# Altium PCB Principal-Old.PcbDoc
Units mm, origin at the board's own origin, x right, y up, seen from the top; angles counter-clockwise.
Board outline 152.4 x 101.6 mm, 2 copper layers (Top Layer, Bottom Layer); 39 components, 56 nets, 199 pads, 48 vias.
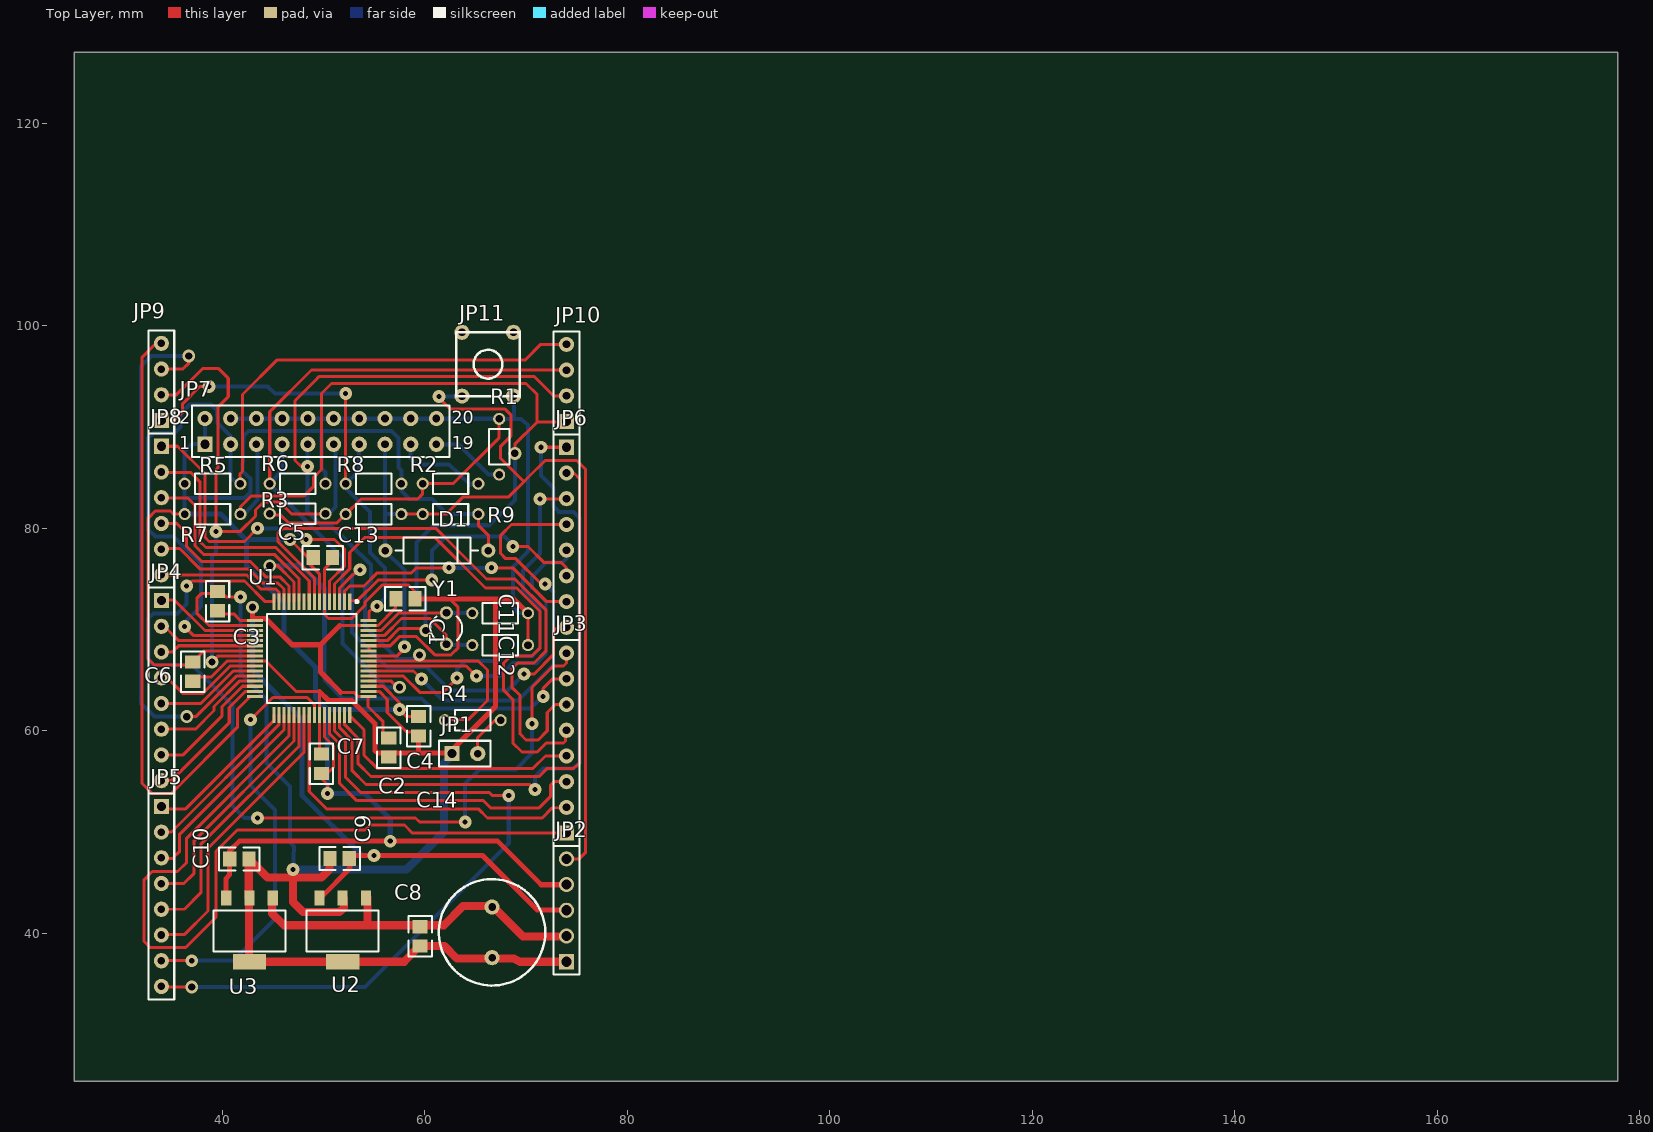
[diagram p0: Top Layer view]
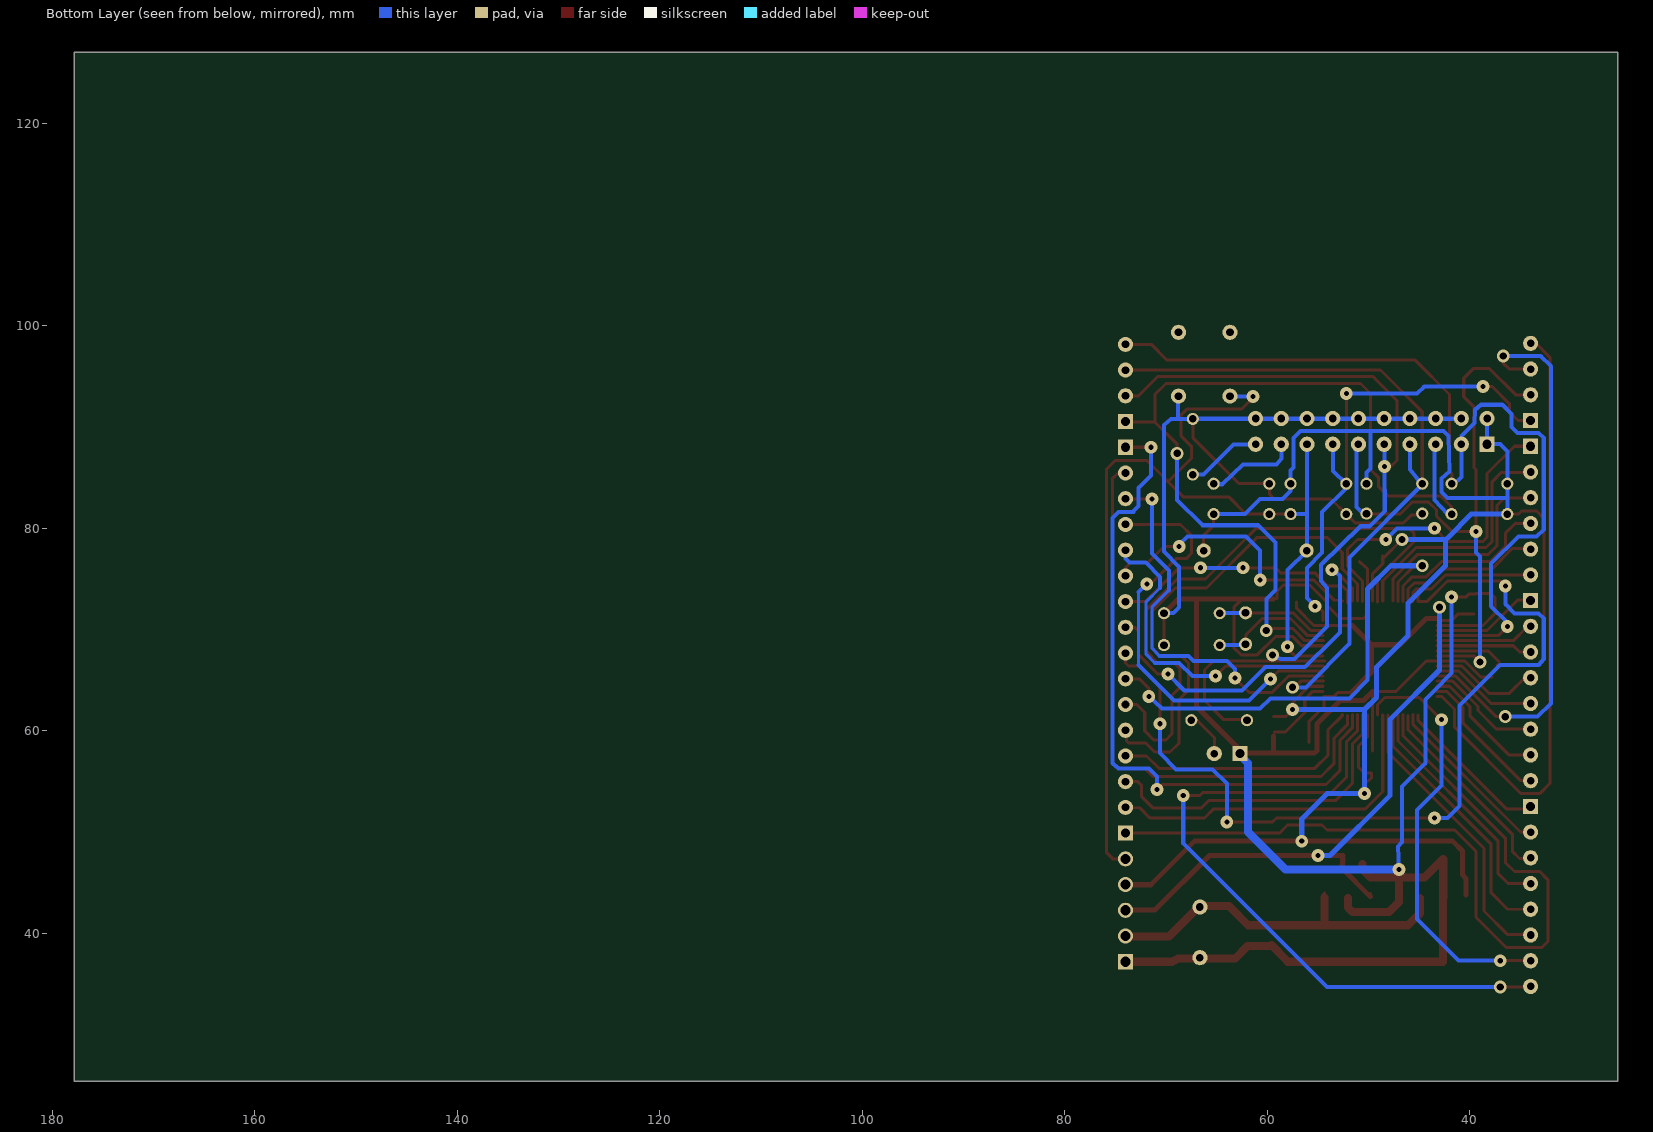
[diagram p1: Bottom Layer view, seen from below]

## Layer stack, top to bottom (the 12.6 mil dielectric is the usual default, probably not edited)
Top Layer: signal copper 0.0356
Dielectric: dielectric 0.32, FR-4, Dk 4.8
Bottom Layer: signal copper 0.0356

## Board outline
25.4,25.4 177.8,25.4 177.8,127 25.4,127

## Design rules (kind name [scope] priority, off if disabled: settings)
Clearance [All] p1: gap=0.2
ComponentClearance [All] p1: gap=0.254 collisioncheckmode=0
PolygonConnect [All] p1: connectstyle=Relief reliefconductorwidth=0.254 reliefentries=4 polygonreliefangle="90 Angle"
RoomDefinition Principal1 [InComponentClass('Principal1')] p1: confinementstyle=ConfineIn formatcopy=TRUE outline 0,0 50.8,0 50.8,25.4 0,25.4
RoutingLayers [All] p1: top layer=Horizontal bottom layer=Vertical
RoutingVias [All] p1: holewidth=0.711 width=1.27 viastyle="Through Hole" minholewidth=0.711 minwidth=1.27 maxholewidth=0.711 maxwidth=1.27
SolderMaskExpansion [All] p1: expansion=0.102
TestPointUsage [All] p1: valid=0 allowmultiple=FALSE
Testpoint [All] p1: side=15 testpointundercomponent=TRUE minsize=1.016 maxsize=2.54 preferedsize=1.524 minholesize=0 maxholesize=1.016 preferedholesize=0.813 testpointgrid=0.025 style=1023 order=1234567890
Width [All] p1: maxlimit=0.8 minlimit=0.2 preferedwidth=0.2 toplayer_prefwidth=0.3 bottomlayer_prefwidth=0.4 minimp=50.000000 maximp=50.000000 favimp=50.000000
16 further rules are at their usual default settings.

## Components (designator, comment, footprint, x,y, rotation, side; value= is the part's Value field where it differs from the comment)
C1 "Cap" R2012-0805 58.1,73.05 r180 top
C2 "Cap" R2012-0805 56.45,58.35 r90 top
C3 "Cap" R2012-0805 39.55,72.8 r270 top
C4 "Cap" R2012-0805 59.4,60.45 r90 top
C5 "Cap" R2012-0805 49.95,77.1 r180 top
C6 "Cap" R2012-0805 37.1,65.85 r90 top
C7 "Cap" R2012-0805 49.8,56.75 r270 top
C8 "Cap" R2012-0805 59.55,39.7 r90 top
C9 "Cap" R2012-0805 51.6,47.4 r0 top
C10 "Cap" R2012-0805 41.7,47.35 r180 top
C11 "Cap" "Res 5mm" 64.7,71.614 r0 top
C12 "Cap" "Res 5mm" 64.7,68.464 r0 top
C13 "Cap" "Res 5mm" 57.7,81.4 r180 top
C14 "Cap Pol1" RB5-10.5 66.65,40.1 r270 top
D1 "Diode" DIODE-0.4 61.2,77.8 r0 top
JP1 "JTAG" HDR1X2 62.7,57.75 r0 top
JP2 "Header 5" HDR1X5 74,37.2 r90 top
JP3 "Header 8" HDR1X8 74,49.9 r90 top
JP4 "Header 8" HDR1X8 34,72.86 r270 top
JP5 "Header 8" HDR1X8 34,52.54 r270 top
JP6 "Header 8" HDR1X8 74,88 r270 top
JP7 "JTAG P5" HDR2X10 38.3,88.3 r0 top
JP8 "Header 6" HDR1X6 34,88.1 r270 top
JP9 "Header 4" HDR1X4 34,90.64 r90 top
JP10 "Header 4" HDR1X4 74,90.54 r90 top
JP11 "Header 2" SW1 69.4,99.35 r180 top
R1 "Res1" "Res 5mm" 67.35,85.3 r90 top
R2 "Res1" "Res 5mm" 65.3,84.4 r180 top
R3 "Res1" "Res 5mm" 50.2,81.45 r180 top
R4 "Res1" "Res 5mm" 62,61.05 r0 top
R5 "Res1" "Res 5mm" 36.3,84.4 r0 top
R6 "Res1" "Res 5mm" 50.2,84.4 r180 top
R7 "Res1" "Res 5mm" 36.3,81.4 r0 top
R8 "Res1" "Res 5mm" 57.7,84.4 r180 top
R9 "Res1" "Res 5mm" 59.8,81.4 r0 top
U1 "LPC2114/LPC2124" F-QFP10X10-G64/P.5N 48.85,67.15 r270 top
U2 "LD1117S18" SOT223 58,37.2 r180 top
U3 "LD1117S33" SOT223 48.8,37.2 r180 top
Y1 "XTAL 16Mhz" BCY-W2/D3.1 62.15,70.1 r180 top

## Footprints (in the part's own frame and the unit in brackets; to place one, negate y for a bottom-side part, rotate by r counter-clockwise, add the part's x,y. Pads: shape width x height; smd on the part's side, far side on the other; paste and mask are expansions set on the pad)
BCY-W2/D3.1 [mm]
  round 1.3 hole 0.75: 1(0,1.55) 2(0,-1.55)
  silkscreen extent -1.55,-1.19 1.55,1.17
DIODE-0.4 [mm]
  round 1.4 hole 0.75: 1(-5.08,0) 2(5.08,0)
  silkscreen extent -4.06,-1.27 4.06,1.27
F-QFP10X10-G64/P.5N [mm]
  rect 1.6x0.3 smd: 1(-5.6,3.75) 2(-5.6,3.25) 3(-5.6,2.75) 4(-5.6,2.25) 5(-5.6,1.75) 6(-5.6,1.25) 7(-5.6,0.75) 8(-5.6,0.25) 9(-5.6,-0.25) 10(-5.6,-0.75) 11(-5.6,-1.25) 12(-5.6,-1.75) 13(-5.6,-2.25) 14(-5.6,-2.75) 15(-5.6,-3.25) 16(-5.6,-3.75) 33(5.6,-3.75) 34(5.6,-3.25) 35(5.6,-2.75) 36(5.6,-2.25) 37(5.6,-1.75) 38(5.6,-1.25) 39(5.6,-0.75) 40(5.6,-0.25) 41(5.6,0.25) 42(5.6,0.75) 43(5.6,1.25) 44(5.6,1.75) 45(5.6,2.25) 46(5.6,2.75) 47(5.6,3.25) 48(5.6,3.75)
  rect 0.3x1.6 smd: 17(-3.75,-5.6) 18(-3.25,-5.6) 19(-2.75,-5.6) 20(-2.25,-5.6) 21(-1.75,-5.6) 22(-1.25,-5.6) 23(-0.75,-5.6) 24(-0.25,-5.6) 25(0.25,-5.6) 26(0.75,-5.6) 27(1.25,-5.6) 28(1.75,-5.6) 29(2.25,-5.6) 30(2.75,-5.6) 31(3.25,-5.6) 32(3.75,-5.6) 49(3.75,5.6) 50(3.25,5.6) 51(2.75,5.6) 52(2.25,5.6) 53(1.75,5.6) 54(1.25,5.6) 55(0.75,5.6) 56(0.25,5.6) 57(-0.25,5.6) 58(-0.75,5.6) 59(-1.25,5.6) 60(-1.75,5.6) 61(-2.25,5.6) 62(-2.75,5.6) 63(-3.25,5.6) 64(-3.75,5.6)
  silkscreen extent -5.72,-4.4 4.4,4.58
HDR1X2 [mm]
  rect 1.5x1.5 hole 0.9: 1(0,0)
  round 1.5 hole 0.75: 2(2.54,0)
  silkscreen extent -1.27,-1.27 3.81,1.27
HDR1X4 [mm]
  rect 1.5x1.5 hole 0.9: 1(0,0)
  round 1.5 hole 0.75: 2(2.54,0) 3(5.08,0) 4(7.62,0)
  silkscreen extent -1.27,-1.27 8.89,1.27
HDR1X5 [mm]
  rect 1.5x1.5 hole 1: 1(0,0)
  round 1.5 hole 1: 2(2.54,0) 3(5.08,0) 4(7.62,0) 5(10.16,0)
  silkscreen extent -1.27,-1.27 11.43,1.27
HDR1X6 [mm]
  rect 1.5x1.5 hole 0.9: 1(0,0)
  round 1.5 hole 0.75: 2(2.54,0) 3(5.08,0) 4(7.62,0) 5(10.16,0) 6(12.7,0)
  silkscreen extent -1.27,-1.27 13.97,1.27
HDR1X8 [mm]
  rect 1.5x1.5 hole 0.9: 1(0,0)
  round 1.5 hole 0.75: 2(2.54,0) 3(5.08,0) 4(7.62,0) 5(10.16,0) 6(12.7,0) 7(15.24,0) 8(17.78,0)
  silkscreen extent -1.27,-1.27 19.05,1.27
HDR2X10 [mm]
  rect 1.5x1.5 hole 0.9: 1(0,0)
  round 1.5 hole 0.75: 2(0,2.54) 3(2.54,0) 4(2.54,2.54) 5(5.08,0) 6(5.08,2.54) 7(7.62,0) 8(7.62,2.54) 9(10.16,0) 10(10.16,2.54) 11(12.7,0) 12(12.7,2.54) 13(15.24,0) 14(15.24,2.54) 15(17.78,0) 16(17.78,2.54) 17(20.32,0) 18(20.32,2.54) 19(22.86,0) 20(22.86,2.54)
  silkscreen extent -1.27,-1.27 24.13,3.81
R2012-0805 [mm]
  rect 1.3x1.5 smd: 1(-0.95,0) 2(0.95,0)
  silkscreen extent -2,-1.15 2,1.15
RB5-10.5 [mm]
  round 1.5 hole 0.75: 1(-2.5,0) 2(2.5,0)
  silkscreen extent -5.25,-5.25 5.25,5.25
"Res 5mm" [mm]
  round 1.2 hole 0.75: 1(0,0) 2(5.5,0)
  silkscreen extent 1,-1.02 4.5,1.02
SOT223 [mm]
  rect 1x1.5 smd: 1(3.8,-6.3) 3(8.4,-6.3) 4(6.1,-6.3)
  rect 3.3x1.5 smd: 4(6.096,0)
  silkscreen extent 2.54,-5.08 9.65,-1.02
SW1 [mm]
  round 1.5 hole 0.75: 1(0.635,6.3) 1(0.635,0) 2(5.715,6.3) 2(5.715,0)
  silkscreen extent 0,0 6.3,6.3

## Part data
C1 C2 C3 C4 C5 C6 C7 C8 C9 C10 C11 C12 C13: "Capacitor"
C14: "Polarized Capacitor (Radial)"
D1: "Default Diode"
JP1 JP2: library part "Header 2", "Header, 2-Pin"
JP3 JP4 JP5 JP6: "Header, 8-Pin"
JP7: library part "Header 10X2", "Header, 10-Pin, Dual row"
JP8: "Header, 6-Pin"
JP9: library part "Header 8", "Header, 8-Pin"
JP10: "Header, 4-Pin"
JP11: "Header, 2-Pin"
R1 R2 R3 R4 R5 R6 R7 R8 R9: "Resistor"
U2 U3: library part LF27ACDT, "Very Low Drop Voltage Regulator with Inhibit"
Y1: library part XTAL, "Crystal Oscillator"

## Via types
v1: diameter 1.27, hole 0.5, Top Layer to Bottom Layer, 37 vias
v2: diameter 1.27, hole 0.711, Top Layer to Bottom Layer, 11 vias

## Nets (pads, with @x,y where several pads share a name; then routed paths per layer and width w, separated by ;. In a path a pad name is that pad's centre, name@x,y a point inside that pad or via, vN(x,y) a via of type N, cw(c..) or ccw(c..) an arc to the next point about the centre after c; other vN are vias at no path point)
GND: C1.1 C2.1 C3.1 C4.1 C5.1 C6.1 C7.1 C8.1 C9.1 C10.1 C11.2 C12.2 C13.2 C14.2 JP1.1 JP2.1 JP7.4 JP7.6 JP7.8 JP7.10 JP7.12 JP7.14 JP7.16 JP7.18 JP7.20 JP11.1@68.765,93.05 R1.2 R2.2 R3.2 U1.6 U1.18 U1.25 U1.42 U1.50 U1.58 U1.59 U2.4 U3.4 | length 319.4
  Top Layer w0.3: C6.1@37.8,65.3 38.9,65.3 40.5,66.9 U1.25 44.3,66.9 47.3,63.9 49.6,63.9 C7.1@49.6,58 ; v1@42.1,73.2 40.4,73.2 40.1,73.5 39.45,73.5 39.4,73.55 37.95,73.55 37.5,73.1 37.5,71.6 38.7,70.4 41.5,70.4 U1.18 ; R3.2@44.85,81.3 45.8,81.3 46.6,80.5 51.3,80.5 C13.2 53.7,82.9 59.3,82.9 59.8,83.4 R2.2 62.8,84.4 67.35,88.95 R1.2@67.35,90.3 ; C5.1@50.9,76.7 50.826,76.635 50.1,76 50.1,71.5 50.5,71.1 52.8,71.1 54.1,72.4 54.1,72.7 55.8,74.4 58.4,74.4 59.05,73.75 C1.1 ; U1.50@54.5,63.9 55.5,63.9 56.3,63.1 56.3,61.8 58.2,59.9 C4.1@59.3,59.9 ; U1.58@54.5,67.9 54.5,68.4 56.6,68.4 57.5,69.3 59.2,69.3 61,67.5 62.6,67.5 63.3,68.2 63.3,72.2 62.5,73 ; JP7.20@61.144,90.816 JP7.20@61.144,90.83 ; C12.2 C11.2
  Top Layer w0.5: 49.6,63.9 50.5,63 52.8,63 55.1,60.7 55.1,58 55.4,57.8 JP1.1@62.3,57.8 ; 59.4,57.8 C4.1 ; C1.1@59.4,73 67,73 ; JP1.1 JP1.1@62.3,57.8 ; C11.2 68.814,73 67,73 ; JP1.1@62.3,57.8 62.7,58.1 67,62.4 67,73
  Top Layer w0.8: C10.1@42.626,47.348 42.626,43.524 42.654,43.496 42.654,37.2 52.054,37.2 58,37.2 58,37.25 C8.1@59.6,38.85 ; C10.1@42.637,47.337 44.474,45.5 49.8,45.5 50.6,46.3 C9.1@50.6,46.847 ; 47,45.5 47,43.1 48,42.1 51.6,42.1 52.05,42.55 U2.4@52.05,43.5 ; v1(47,46.3) 47.1,45.5 ; C8.1 61.95,38.75 63.2,37.5 68.8,37.5 69.4,37.2 JP2.1
  Bottom Layer w0.4: JP7.4@40.824,90.816 67.834,90.816 67.85,90.8 69.5,90.8 70.2,90.2 70.2,83.3 70.2,77.7 68.7,76.2 68.7,72.2 69.286,71.614 C11.2 ; v1(41.8,73.2) 41.8,65.7 43.6,63.9 44.4,63.1 44.4,56.8 46.7,54.5 46.7,49 47.1,48.6 v1(47,46.3) ; JP11.1@68.765,93.05 68.8,93.015 68.8,90.8
  Bottom Layer w0.8: v1(47,46.3) 58.2,46.3 61.9,50 61.9,56.8 JP1.1@62.7,57.6
NetC1_2: C1.2 C2.2 C3.2 C9.2 JP2.3 U1.17 U1.49 U1.63 U2.3 | length 95.1
  Top Layer w0.3: C3.2@39.6,71.55 41.15,71.55 41.8,70.9 U1.17@43,70.9 ; 46.4,69 46.9,68.5 ; U2.3@49.834,43.628 U2.3@49.834,43.917 ; 51.6,70.4 55.4,70.4 57.1,72.1 C1.2@57.1,72.7 ; 51.7,63.8 53,63.8 53.4,63.4 U1.49 ; U1.49@54.4,63.4 54.4,62.4 55.9,60.9 C2.2@55.9,58.85
  Top Layer w0.5: v2(43,72.2) 43,71.1 44.3,71.1 46.9,68.5 49.7,68.5 ; U2.3@49.834,43.628 52.6,46.4 C9.2 ; 51.6,70.4 49.7,68.5 ; 51.7,63.8 49.7,65.8 49.7,68.5 ; C9.2@52.55,47.7 v1(55,47.7) 65.7,47.7 71.1,42.3 JP2.3@73.7,42.3
  Bottom Layer w0.5: v2(43,72.2) 43,66 47.9,61.1 47.9,53.6 53.8,47.7 v1(55,47.7)
NetC4_2: C4.2 C5.2 C6.2 C7.2 C10.2 D1.2 JP2.4 JP7.1 JP7.2 R5.1 R6.1 R7.1 R8.1 R9.2 U1.7 U1.23 U1.43 U1.51 U3.3 | length 211.6
  Top Layer w0.3: R7.1 35.2,81.4 34.9,81.7 33.4,81.7 32.7,81 32.7,67.1 33.3,66.5 35.4,66.5 36,66.5 C6.2@37.3,66.5 ; C6.2 38.2,67.9 U1.23 ; v2(46.7,78.9) 48.6,77 C5.2@48.65,76.95 ; C5.2@48.6,77.25 48.6,76.5 49.6,75.5 U1.7@49.6,72.8 ; U1.43 50.1,59.4 51,58.5 51,56.4 50.45,55.85 49.7,55.85 49.7,55.4 50.4,54.7 v1(50.4,53.8) ; U1.51@54.5,64.4 55.9,64.4 57.5,62.8 v1(57.5,62.1) 58.2,61.4 C4.2 ; R9.2 65.3,80.3 66.28,79.32 D1.2
  Top Layer w0.5: U3.3@40.4,43.8 40.4,45.4 40.726,45.775 40.726,48.126 41.7,49.1 67.2,49.1 71.5,44.8 JP2.4@73.7,44.8
  Bottom Layer w0.4: R7.1 36.3,84.2 36.3,87.6 37,88.3 JP7.1 ; 36.3,83 42.2,83 42.8,83.6 42.8,84.9 42,85.6 42.1,89.1 42.6,89.6 56.7,89.6 56.8,89.5 57.4,88.9 57.4,86 57.7,85.7 57.7,83.7 58.5,82.9 60.7,82.9 62.2,81.4 R9.2 ; JP7.1@38.284,88.276 JP7.2@38.284,90.816 ; 49.8,89.5 49.8,85.9 50.2,85.5 R6.1@50.2,84.35
  Bottom Layer w0.5: R7.1 39.9,81.4 42.1,79.1 42.4,78.9 ; v2(46.7,78.9) 42.4,78.9 ; v1(56.6,49.1) 56.6,51.3 54.1,53.8 v1(50.4,53.8) 50.4,62.1 ; v1(57.5,62.1) 56.059,62.104 53.9,62.1 50.4,62.1 ; 42.4,78.9 42.4,76.3 46.1,72.6 46.1,69.4 49.2,66.3 49.2,63.3 50.4,62.1
NetC8_2: C8.2 C14.1 JP2.2 U2.1 U3.1 | length 36.1
  Top Layer w0.3: U2.1@54.334,44.009 54.334,43.79 U2.1@54.553,43.79
  Top Layer w0.8: U3.1@44.95,43.5 44.934,41.966 46.1,40.8 61.9,40.8 63.8,42.7 66.7,42.7 69.7,39.7 JP2.2@73.8,39.7 ; 54.3,40.8 54.35,40.85 U2.1@54.35,43.55
NetC11_1: C11.1 U1.62 Y1.2 | length 11
  Top Layer w0.3: U1.62@54.5,69.9 55.7,69.9 57.414,71.614 Y1.2@62.114,71.614 ; C11.1 C11.1@64.75,71.664
  Bottom Layer w0.4: Y1.2@62.114,71.614 C11.1
NetC12_1: C12.1 U1.61 Y1.1 | length 12.5
  Top Layer w0.3: U1.61@54.5,69.4 56,69.4 57.7,71.1 60.5,71.1 62.1,69.5 62.184,68.55 Y1.1@62.184,68.514 ; C12.1@64.65,68.514 C12.1
  Bottom Layer w0.4: Y1.1@62.236,68.464 C12.1
NetC13_1: C13.1 D1.1 JP2.5 JP7.15 JP11.2@63.685,93.05 R9.1 U1.57 | length 105.3
  Top Layer w0.3: U1.57@54.5,67.4 57.3,67.4 58,68.1 v1(58,68.3) ; C13.1 62.1,81.4 63.8,83.1 68.3,83.1 69.8,84.6 ; v1@61.4,92.9 62.5,91.8 67.9,91.8 68.5,91.2 68.5,89.1 67.5,88.1 67.5,86.9 69.8,84.6 ; JP2.5 75.26,47.36 75.9,48 75.9,85.8 75,86.7 71.9,86.7 70.21,85.01 69.8,84.6
  Bottom Layer w0.4: 56.064,81.4 C13.1 ; JP7.15@56.064,88.276 56.064,77.806 56.095,77.775 58,75.9 v1(58,68.3) ; D1.1 D1.1@56.3,77.8 ; v1(61.4,93) JP11.2@63.635,93
NetJP1_2: JP1.2 R4.2 | length 4.3
  Top Layer w0.3: JP1.2 65.2,59.3 66.9,61 R4.2@67.2,61
NetJP3_1: JP3.1 U1.36 | length 80.9
  Top Layer w0.3: U1.36@46.6,61.625 46.6,59.5 36.5,49.4 36.5,47 35.6,46.1 33.1,46.1 32.3,45.3 32.3,39.2 32.9,38.6 36.4,38.6 39.4,41.6 39.4,48.1 41.5,50.2 54.1,50.2 54.6,50.7 58,50.7 58.8,49.9 JP3.1
NetJP3_2: JP3.2 U1.40 | length 34.4
  Top Layer w0.3: U1.40 48.6,60.409 48.6,54 50.3,52.3 65.3,52.3 66.2,51.4 71.6,51.4 72.6,52.4 JP3.2
NetJP3_3: JP3.3 U1.44 | length 32.3
  Top Layer w0.3: U1.44@50.6,61.6 50.6,59.7 51.6,58.7 51.6,54.8 53.3,53.1 65.8,53.1 66.5,52.4 71.3,52.4 72.4,53.5 72.4,54.6 72.78,54.98 JP3.3
NetJP3_4: JP3.4 U1.48 | length 25.6
  Top Layer w0.3: U1.48@52.6,61.6 52.6,61.5 54,60.1 54,57.6 55.3,56.3 70.7,56.3 71.92,57.52 JP3.4
NetJP3_5: JP3.5 U1.4 | length 51.1
  Top Layer w0.3: U1.4@51.1,72.8 51.1,74.5 52.6,76 52.6,77.6 54.1,79.1 61,79.1 66,74.1 69.093,74.1 71.4,71.793 71.4,68.2 70.6,67.4 68.5,67.4 67.8,66.7 67.8,64 68.7,63.1 68.7,58.8 69.6,57.9 71.1,57.9 72,58.8 73.7,58.8 73.9,59 73.9,59.96 JP3.5
NetJP3_6: JP3.6 U1.8 | length 61.1
  Top Layer w0.3: U1.8@49.1,72.7 49.1,75.1 45.5,78.7 45.5,79.5 46,80 61.1,80 62.9,78.2 66.1,75 68.9,75 72,71.9 72,67.9 70.8,66.7 69.2,66.7 68.6,66.1 68.6,64.3 69.4,63.5 69.4,59.7 70,59.1 71.2,59.1 72.1,60 72.1,61.8 72.9,62.6 JP3.6 JP3.6@74,62.1
NetJP3_7: JP3.7 U1.12 | length 47.1
  Top Layer w0.3: v2(44.7,76.3) 45.5,76.3 47.1,74.7 U1.12 ; v1(71.7,63.4) 71.7,64.2 72.64,65.14 JP3.7
  Bottom Layer w0.4: 50.1,69.1 50.1,65 51.9,63.2 59.7,63.2 60.7,62.2 70.4,62.2 v1(71.7,63.4)
  Bottom Layer w0.5: v2(44.7,76.3) 47.8,76.3 50.1,74 50.1,69.1
NetJP3_8: JP3.8 U1.16 | length 87.9
  Top Layer w0.3: v1(36.5,74.3) 37,74.8 42.2,74.8 44.25,72.75 U1.16 ; v1(43.5,51.4) 59.1,51.4 59.5,51 v1(64,51) ; U1.16@45.1,72.8 U1.16@45.1,73.4 ; v1(70.6,60.7) 70.6,64.3 72.7,66.4 73.7,66.4 74,66.7 JP3.8 JP3.8@73.98,67.68
  Bottom Layer w0.4: v1(36.5,74.3) 36.5,72.5 35.6,71.6 33.2,71.6 32.7,71.1 32.7,67.1 33.2,66.5 37,66.5 41,62.5 41,52.6 42.2,51.4 v1(43.5,51.4) ; v1(64,51) 64,54.8 65.4,56.2 69,56.2 70.6,57.8 v1(70.6,60.7) v1@70.7,60.8
NetJP4_1: JP4.1 U1.19 | length 10.1
  Top Layer w0.3: JP4.1@34.4,72.9 35.3,72.9 38.3,69.9 41.1,69.9 U1.19
NetJP4_2: JP4.2 U1.21 | length 9.8
  Top Layer w0.3: JP4.2 34.4,70.2 35.7,68.9 36.9,68.9 40.4,68.9 U1.21
NetJP4_3: JP4.3 U1.22 | length 9.2
  Top Layer w0.3: JP4.3@34.3,67.8 35.1,67.8 35.7,68.4 37.3,68.4 40.1,68.4 U1.22
NetJP4_4: JP4.4 U1.26 | length 11
  Top Layer w0.3: JP4.4 34.56,65.24 36.1,63.7 38.1,63.7 40.8,66.4 U1.26
NetJP4_5: JP4.5 U1.27 | length 10.1
  Top Layer w0.3: JP4.5@34.5,62.7 37.9,62.7 41.1,65.9 U1.27
NetJP4_6: JP4.6 U1.29 | length 11.4
  Top Layer w0.3: JP4.6 37.36,60.16 39.2,62 39.2,62.4 41.7,64.9 U1.29
NetJP4_7: JP4.7 U1.30 | length 12.4
  Top Layer w0.3: JP4.7@34.2,57.6 36.1,57.6 40,61.5 40,62.4 42,64.4 U1.30
NetJP4_8: JP4.8 U1.31 | length 13.8
  Top Layer w0.3: JP4.8 34.98,55.08 40.7,60.8 40.7,62.3 42.3,63.9 U1.31
NetJP5_1: JP5.1 U1.33 | length 15
  Top Layer w0.3: JP5.1@34.3,52.3 36.4,52.3 45.1,61 U1.33
NetJP5_2: JP5.2 U1.34 | length 17
  Top Layer w0.3: JP5.2 35,50 45.6,60.6 U1.34 U1.34@45.6,61.625
NetJP5_3: JP5.3 U1.35 | length 19.6
  Top Layer w0.3: JP5.3@34.2,47.4 35.1,47.4 35.8,48.1 35.8,49.8 46.1,60.1 U1.35@46.1,61.525
NetJP5_4: JP5.4 U1.37 | length 23.4
  Top Layer w0.3: JP5.4 36.22,44.92 37.2,45.9 37.2,49.1 47.1,59 U1.37
NetJP5_5: JP5.5 U1.38 | length 27
  Top Layer w0.3: JP5.5 36.3,42.4 37.9,44 37.9,48.8 47.6,58.5 U1.38 47.6,60.709
NetJP5_6: JP5.6 U1.39 | length 28.6
  Top Layer w0.3: JP5.6@34.2,39.9 36.3,39.9 38.6,42.2 38.6,48.4 48.1,57.9 U1.39
NetJP5_7: JP5.7 U1.41 | length 41.8
  Top Layer w0.3: JP5.7@34.3,37.3 v1(37,37.3) ; v1(42.8,61.1) 43.6,61.9 45,63.3 48.4,63.3 49.1,62.6 U1.41
  Bottom Layer w0.4: v1(37,37.3) 41.1,37.3 45.2,41.4 45.2,52.2 42.8,54.6 v1(42.8,61.1)
NetJP5_8: JP5.8 U1.45 | length 68.1
  Top Layer w0.3: JP5.8@34.3,34.7 v2(37,34.7) ; U1.45@51.1,61.6 51.1,60 52.2,58.9 52.2,55.4 53.7,53.9 66.4,53.9 66.7,53.6 v1(68.3,53.6)
  Bottom Layer w0.4: v2(37,34.7) 54.1,34.7 68.3,48.9 v1(68.3,53.6)
NetJP6_1: JP6.1 U1.46 | length 67.2
  Top Layer w0.3: U1.46@51.6,61.6 51.6,60.3 52.8,59.1 52.8,56.1 54.2,54.7 70.4,54.7 v1(70.9,54.2) ; v1(71.5,88) JP6.1
  Bottom Layer w0.4: v1(70.9,54.2) 70.9,55.5 71.7,56.3 74.7,56.3 75.3,56.8 75.3,81 74.7,81.6 73.2,81.6 73.2,81.7 72.7,82.2 72.7,84 71.5,85.2 v1(71.5,88)
NetJP6_2: JP6.2 U1.47 | length 57.5
  Top Layer w0.3: U1.47@52.1,61.5 52.1,60.6 53.4,59.3 53.4,56.8 54.7,55.5 71.3,55.5 72.1,56.3 74.7,56.3 75.3,56.8 75.3,84.9 74.8,85.4 JP6.2@74.3,85.4
NetJP6_3: JP6.3 U1.53 | length 38.6
  Top Layer w0.3: U1.53@54.5,65.4 57.9,65.4 59.5,63.8 61.8,63.8 v1(63.2,65.2) ; v1(71.4,82.9) JP6.3@73.98,82.9
  Bottom Layer w0.3: 69.719,73.881 71.4,72.2 71.4,68.2 70.651,67.4
  Bottom Layer w0.4: v1(63.2,65.2) 63.2,66.1 64,66.9 67.3,66.9 67.8,67.4 70.651,67.4 ; 69.719,73.881 69.719,75.819 71.4,77.5 v1(71.4,82.9)
NetJP6_4: JP6.4 U1.54 | length 43.6
  Top Layer w0.3: U1.54@54.5,65.9 58.9,65.9 v1(59.7,65.1) ; v1(71.9,74.5) 71.5,74.5 69,77 68,77 67.5,77.5 67.5,79.3 68.58,80.38 JP6.4
  Bottom Layer w0.3: 72.7,66.5 72.7,73.7
  Bottom Layer w0.4: v1(59.7,65.1) 61.8,63 69.2,63 72.7,66.5 ; v1(71.9,74.5) 72.7,73.7
NetJP6_5: JP6.5 U1.55 | length 32
  Top Layer w0.3: U1.55 64.1,66.4 v1(65.1,65.4)
  Bottom Layer w0.3: 70.6,74.1 72,72.7 72,67.6 71.1,66.7
  Bottom Layer w0.4: v1(65.1,65.4) 66.1,65.4 67.4,65.4 68.7,66.7 71.1,66.7 ; 70.6,74.1 70.6,75.2 72,76.6 73.6,76.6 74,77 JP6.5
NetJP6_6: JP6.6 U1.1 | length 27.9
  Top Layer w0.3: U1.1@52.6,72.8 53.4,72.9 55.4,74.9 v1(60.7,74.9) ; v1(68.7,78.2) 70.2,78.2 71.8,76.6 73.5,76.6 74,76.1 JP6.6
  Bottom Layer w0.4: v1(60.7,74.9) 60.7,77.8 62.1,79.2 67.9,79.2 68.7,78.4 v1(68.7,78.2)
NetJP6_7: JP6.7 U1.2 | length 25.4
  Top Layer w0.3: U1.2@52.1,72.6 52.1,73.8 52.6,74.3 54,74.3 55.3,75.6 58.7,75.6 59.2,76.1 v1(62.4,76.1) ; v1(66.6,76.1) 68.7,76.1 72.04,72.76 JP6.7
  Bottom Layer w0.4: v1(62.4,76.1) v1(66.6,76.1)
NetJP6_8: JP6.8 U1.3 | length 38.5
  Top Layer w0.3: U1.3@51.6,72.8 51.6,74.1 52.9,75.4 v1(53.6,75.9) ; v1(69.8,65.6) 70.8,65.6 72.7,67.5 72.7,69.8 73.12,70.22 JP6.8 JP6.8@73.72,70.5
  Bottom Layer w0.4: v1(53.6,75.9) 52.8,75.3 52.8,69.7 53.5,69 56.3,66.3 60.2,66.3 62.5,64 68.2,64 v1(69.8,65.6)
NetJP7_3: JP7.3 JP10.4 R5.2 U1.20 | length 90.8
  Top Layer w0.3: v1(36.3,70.3) 37.2,69.4 40.8,69.4 U1.20 ; R5.2@41.75,84.2 41.75,85.35 42,85.6 42,93.2 45.4,96.6 69.9,96.6 71.46,98.16 JP10.4
  Bottom Layer w0.4: v1(36.3,70.3) 36.3,70.7 37.9,72.3 37.9,76.5 35.2,79.2 33.4,79.2 32.7,79.9 32.7,88.9 33.2,89.4 35.3,89.4 35.9,90 35.9,91.3 36.8,92.2 38.9,92.2 39.5,91.7 39.548,90.379 40.824,89.103 40.824,85.076 41.677,84.269 41.75,84.2 R5.2@41.45,84.35
NetJP7_5: JP7.5 JP10.1 R7.2 U1.60 | length 88.9
  Top Layer w0.3: R7.2 41.8,82.1 42.9,83.2 48.1,83.2 49,84.1 49,85 49.8,85.8 49.8,93.3 50.8,94.3 70,94.3 71.1,93.2 71.1,91.5 71.1,90.5 ; U1.60 56.3,68.9 57.5,70.1 59.8,70.1 v2(60.1,69.9) ; v2(68.9,87.4) 68.9,88.3 71.1,90.5 ; JP10.1@73.7,90.5 71.1,90.5
  Bottom Layer w0.4: R7.2 42.2,81.4 43.5,82.8 43.5,88.18 JP7.5 ; JP7.5@43.364,88.276 JP7.5@43.383,88.276 ; v2(60.1,69.9) 60.1,73 59.2,73.9 59.2,78.6 60.9,80.3 66.4,80.3 68.9,82.8 v2(68.9,87.4)
NetJP7_7: JP7.7 JP10.3 R6.2 U1.52 | length 71.9
  Top Layer w0.3: R6.2@44.65,84.35 44.7,84.6 44.7,91.5 48.82,95.62 JP10.3 ; U1.52 56.7,64.9 v2@57.3,64.3
  Bottom Layer w0.4: R6.2 R6.2@44.7,84.3 ; JP7.7@45.9,88.38 45.904,88.276 45.904,85.804 44.749,84.361 R6.2@44.7,84.3 ; v2(57.5,64.3) 56.2,64.3 51.9,68.6 51.9,77.1 R6.2@44.7,84.3
NetJP7_9: JP7.9 JP10.2 R4.1 U1.56 | length 85.5
  Top Layer w0.3: v1@48.9,86.1 47.8,86.1 47.2,86.7 47.2,92.6 49.2,94.6 49.6,95 70.8,95 72.72,93.08 JP10.2 ; U1.56@54.3,66.9 65.3,66.9 66.2,66 66.2,63 64.3,61.1 62.3,61.1 R4.1@62,61.1 ; v2@59.5,66.9 v2(59.5,67.5)
  Bottom Layer w0.4: JP7.9@48.444,88.276 48.429,86.1 48.4,81.7 49.9,80.2 50.8,80.2 54.7,76.4 54.7,74.8 54.1,74.1 54.1,70.3 57.3,67.1 58.7,67.1 v2(59.5,67.5)
  other v1: 48.444,86.1
NetJP7_11: JP7.11 JP9.2 R3.1 U1.24 | length 61.5
  Top Layer w0.3: JP9.2 35.48,93.18 38.1,95.8 39.6,95.8 40.6,94.8 40.6,93 39.6,92 39.6,86 39.4,85.8 v1(39.4,79.7) 41.8,79.7 43.3,81.2 43.3,81.8 44.1,82.6 45.7,82.6 46.9,81.4 R3.1@49.9,81.4 ; v2(39,66.8) 39.6,67.4 U1.24 ; R3.1 R3.1@50.4,81.4
  Bottom Layer w0.4: v2(39,66.8) 39,77.2 39.4,77.6 v1(39.4,79.7) ; R3.1@49.9,81.5 50.6,81.5 51.2,82.1 JP7.11@51.2,88
NetJP7_13: JP7.13 JP9.1 R8.2 U1.64 | length 49.7
  Top Layer w0.3: JP9.1 35.24,90.64 36.1,91.5 36.1,92.3 37.8,94 v1(38.7,94) ; R8.2@52.2,84.35 v1(52.2,93.3) ; U1.64@54.5,70.9 54.5,71.8 v1(55.3,72.3)
  Bottom Layer w0.4: v1(38.7,94) 44.5,94 45.2,93.3 v1(52.2,93.3) ; JP7.13@53.416,88.276 53.524,88.276 53.524,85.674 52.2,84.35 52.2,84 54.6,81.6 54.6,77.6 56.1,76.1 56.1,73.1 v1(55.3,72.3)
NetJP7_17: JP7.17 R2.1 | length 9.1
  Bottom Layer w0.4: JP7.17@58.604,88.276 58.604,86.896 59.1,86.3 62.4,86.3 64.45,84.35 R2.1@65.3,84.35
NetJP7_19: JP7.19 R1.1 | length 7.4
  Bottom Layer w0.4: JP7.19@61.144,88.276 63.324,88.276 66.3,85.3 R1.1
NetJP8_1: JP8.1 U1.5 | length 32.9
  Top Layer w0.3: JP8.1 35.6,88.1 38.3,85.4 38.3,79.1 38.7,78.7 42.2,78.7 v1(43.5,80) ; v1(48.3,78.9) 51.1,78.9 52.1,77.9 52.1,76.3 50.6,74.8 U1.5
  Bottom Layer w0.4: v1(43.5,80) 47.2,80 v1(48.3,78.9)
NetJP8_2: JP8.2 U1.9 | length 24.4
  Top Layer w0.3: JP8.2@34.06,85.5 36.9,85.5 37.8,84.6 37.8,78.7 38.4,78.1 45.3,78.1 48.6,74.8 U1.9@48.6,72.8
NetJP8_3: JP8.3 U1.11 | length 21.2
  Top Layer w0.3: JP8.3@34.3,83 36.6,83 37.3,82.3 37.3,78.3 38.2,77.4 45.2,77.4 47.6,75 U1.11@47.6,72.8
NetJP8_4: JP8.4 U1.13 | length 17.5
  Top Layer w0.3: JP8.4 35.48,80.48 ; 35.5,80.5 36.5,79.5 36.5,78.2 38,76.7 42.8,76.7 44.3,75.2 45.7,75.2 46.6,74.3 U1.13
NetJP8_5: JP8.5 U1.14 | length 14.7
  Top Layer w0.3: JP8.5@34.3,78 35.8,78 37.8,76 42.6,76 44,74.6 45.5,74.6 46.1,74 U1.14
NetJP8_6: JP8.6 U1.15 | length 13.6
  Top Layer w0.3: JP8.6@34.3,75.3 JP8.6 42.4,75.4 43.8,74 45.3,74 45.6,73.7 U1.15
NetJP9_3: JP9.3 U1.28 | length 55.5
  Top Layer w0.3: JP9.3 36.12,95.72 36.7,96.3 v2(36.7,97) ; v2(36.5,61.4) 37.4,61.4 41.4,65.4 U1.28
  Bottom Layer w0.4: v2(36.5,61.4) 33.3,61.4 32,62.7 32,96 33,97 v2(36.7,97)
NetJP9_4: JP9.4 U1.32 | length 60.6
  Top Layer w0.3: JP9.4@33.5,98.3 32.1,96.9 32.1,54.8 33.1,53.8 34.95,53.8 41.5,60.35 41.5,62.1 42.8,63.4 U1.32
pads on no net: JP11.1@68.765,99.35 JP11.2@63.685,99.35 U1.10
